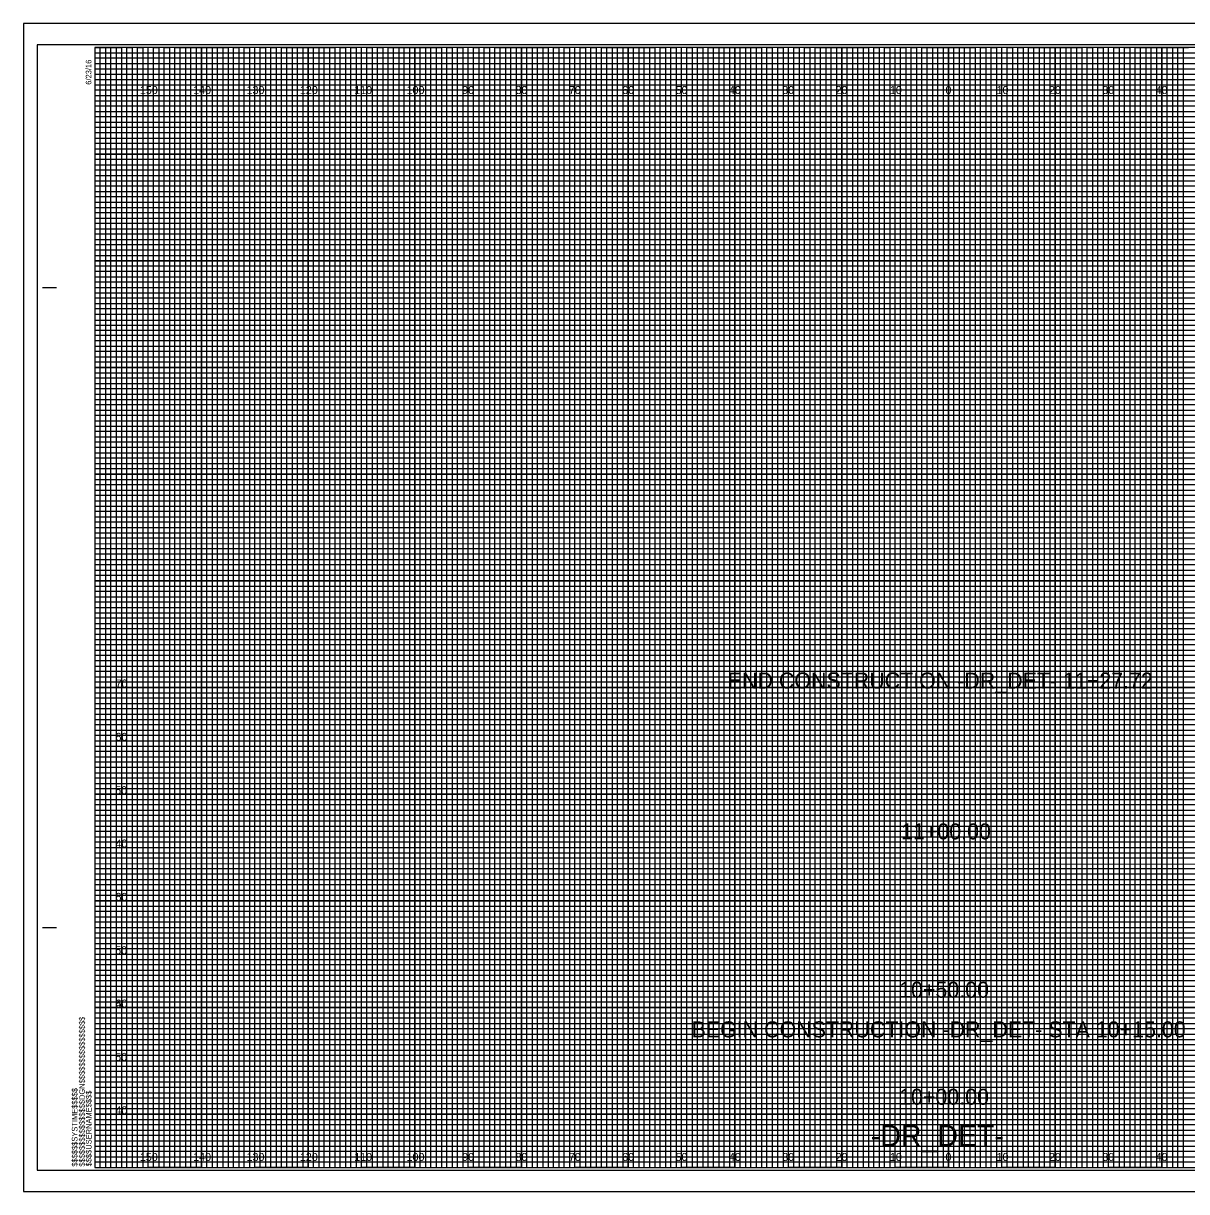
# Model space of a CAD drawing. Extents: x -13 to 323, y -5 to 215.
# Drawn here: x -13.4 to 204.7, y -4.5 to 214.5 of the extents above; entities that cross this region are included whole.
import ezdxf

# ---------------------------------------------------------------- set-up
doc = ezdxf.new("R2010")
doc.units = 0
for name, color, linetype in [('Prop XS Alignment Label', 7, 'Continuous'), ('Prop XS Elevation Labels', 7, 'Continuous'), ('Prop XS Offset Labels', 7, 'Continuous'), ('Prop XS Station Labels', 7, 'Continuous'), ('Sheet Cross Section CELL', 7, 'Continuous'), ('Sheet Cross Section Grid Major CELL', 7, 'Continuous'), ('Sheet Cross Section Grid Middle CELL', 7, 'Continuous'), ('Sheet Cross Section Grid Minor 1 CELL', 7, 'Continuous'), ('Sheet Cross Section Grid Minor 2 CELL', 7, 'Continuous'), ('Sheet Cutting Line CELL', 7, 'Continuous'), ('Sheet DOT Grid CELL', 7, 'Continuous'), ('Sheet Plot Border Inside CELL', 7, 'Continuous'), ('Sheet Plot Border Outside CELL', 7, 'Continuous')]:
    doc.layers.add(name, color=color, linetype=linetype)

msp = doc.modelspace()

# ---------------------------------------------------------------- linework, layer by layer
at = {"layer": 'Sheet Cross Section CELL'}
for p, q in [((-9.8, 165), (-7.3, 165)), ((-9.7, 165), (-7.2, 165)), ((-9.8, 45), (-7.3, 45)), ((-9.7, 45), (-7.2, 45)), ((0, 0), (0, 0)), ((0, 0), (0, 0)), ((0, 0), (0, 0)), ((0, 0), (0, 0)), ((0, 0), (0, 0)), ((0, 0), (0, 0)), ((0, 0), (0, 0))]:
    msp.add_line(p, q, dxfattribs=at)
msp.add_lwpolyline([(320, 210), (0, 210), (0, 0), (320, 0)], close=True, dxfattribs=at)
at = {"layer": 'Sheet Cross Section Grid Major CELL'}
for p, q in [((10, 210), (0, 210)), ((10, 0), (10, 210)), ((30, 210), (20, 210)), ((20, 210), (20, 0)), ((30, 0), (30, 210)), ((50, 210), (40, 210)), ((40, 210), (40, 0)), ((50, 0), (50, 210)), ((70, 210), (60, 210)), ((60, 210), (60, 0)), ((70, 0), (70, 210)), ((90, 210), (80, 210)), ((80, 210), (80, 0)), ((90, 0), (90, 210)), ((110, 210), (100, 210)), ((100, 210), (100, 0)), ((110, 0), (110, 210)), ((130, 210), (120, 210)), ((120, 210), (120, 0)), ((130, 0), (130, 210)), ((150, 210), (140, 210)), ((140, 210), (140, 0)), ((150, 0), (150, 210)), ((170, 210), (160, 210)), ((160, 210), (160, 0)), ((170, 0), (170, 210)), ((190, 210), (180, 210)), ((180, 210), (180, 0)), ((190, 0), (190, 210)), ((210, 210), (200, 210)), ((200, 210), (200, 0)), ((20, 0), (10, 0)), ((40, 0), (30, 0)), ((60, 0), (50, 0)), ((80, 0), (70, 0)), ((100, 0), (90, 0)), ((120, 0), (110, 0)), ((140, 0), (130, 0)), ((160, 0), (150, 0)), ((180, 0), (170, 0)), ((200, 0), (190, 0))]:
    msp.add_line(p, q, dxfattribs=at)
for points in [[(0, 200), (320, 200), (320, 190), (0, 190)], [(0, 180), (320, 180), (320, 170), (0, 170)], [(0, 160), (320, 160), (320, 150), (0, 150)], [(0, 140), (320, 140), (320, 130), (0, 130)], [(0, 120), (320, 120), (320, 110), (0, 110)], [(0, 100), (320, 100), (320, 90), (0, 90)], [(0, 80), (320, 80), (320, 70), (0, 70)], [(0, 60), (320, 60), (320, 50), (0, 50)], [(0, 40), (320, 40), (320, 30), (0, 30)], [(0, 20), (320, 20), (320, 10), (0, 10)]]:
    msp.add_lwpolyline(points, dxfattribs=at)
at = {"layer": 'Sheet Cross Section Grid Middle CELL'}
for points in [[(0, 210), (5, 210), (5, 0), (15, 0), (15, 210), (25, 210), (25, 0), (35, 0), (35, 210), (45, 210), (45, 0), (55, 0), (55, 210), (65, 210), (65, 0), (75, 0), (75, 210), (85, 210), (85, 0), (95, 0), (95, 210), (105, 210), (105, 0), (115, 0), (115, 210), (125, 210), (125, 0), (135, 0), (135, 210), (145, 210), (145, 0), (155, 0), (155, 210), (165, 210), (165, 0), (175, 0), (175, 210), (185, 210), (185, 0), (195, 0), (195, 210), (205, 210)], [(0, 205), (275, 205)], [(0, 185), (320, 185), (320, 195), (0, 195)], [(0, 165), (320, 165), (320, 175), (0, 175)], [(0, 145), (320, 145), (320, 155), (0, 155)], [(0, 125), (320, 125), (320, 135), (0, 135)], [(0, 105), (320, 105), (320, 115), (0, 115)], [(0, 85), (320, 85), (320, 95), (0, 95)], [(0, 65), (320, 65), (320, 75), (0, 75)], [(0, 45), (320, 45), (320, 55), (0, 55)], [(0, 25), (320, 25), (320, 35), (0, 35)], [(0, 5), (320, 5), (320, 15), (0, 15)]]:
    msp.add_lwpolyline(points, dxfattribs=at)
at = {"layer": 'Sheet Cross Section Grid Minor 1 CELL'}
for p, q in [((0, 209), (260, 209)), ((260, 207.98), (0, 207.98)), ((0, 207.98), (0, 207)), ((0, 207), (260, 207)), ((260, 205.89), (0, 205.89)), ((0, 205.89), (0, 204)), ((0, 204), (320, 204))]:
    msp.add_line(p, q, dxfattribs=at)
for points in [[(0, 203), (270, 203), (320, 203), (320, 202), (0, 202)], [(0, 201), (320, 201), (320, 199), (0, 199)], [(0, 198), (320, 198), (320, 197), (0, 196.98)], [(0, 196), (320, 196), (320, 194), (0, 194)], [(0, 193), (320, 193), (320, 192), (0, 192)], [(0, 191), (320, 191), (320, 189), (0, 189)], [(0, 188), (320, 188), (320, 187), (0, 187)], [(0, 186), (320, 186), (320, 184), (0, 184)], [(0, 183), (320, 183), (320, 182), (0, 182)], [(0, 181), (320, 181), (320, 179), (0, 179)], [(0, 178), (320, 178), (320, 177), (0, 177)], [(0, 176), (320, 176), (320, 173.95), (320, 173), (320, 172), (0, 172)], [(0, 174), (320, 174), (320, 173), (0, 173)], [(0, 171), (320, 171), (320, 169), (0, 169.03)], [(0, 169.03), (320, 169), (320, 168), (0, 168)], [(0, 167), (320, 167), (320, 166), (0, 166)], [(0, 164), (320, 164), (320, 163), (0, 163)], [(0, 162), (320, 162), (320, 161), (0, 161)], [(-0.07, 158.89), (320, 158.89), (320, 157.88), (-0.07, 157.88)], [(0, 157), (320, 157), (320, 156), (0, 156)], [(0, 154), (320, 154), (320, 153), (0, 153)], [(0, 152), (320, 152), (320, 151), (0, 151)], [(0, 149), (320, 149), (320, 148), (0, 148)], [(0, 147), (320, 147), (320, 146), (0, 146)], [(0, 144), (320, 144), (320, 143), (0, 143)], [(0, 142), (320, 142), (320, 141), (0, 141)], [(0, 139), (320, 139), (319.99, 137.98), (0, 138)], [(0, 137), (320, 137), (320, 136), (0, 136)], [(0, 134), (320, 134), (320, 133), (0, 133)], [(0, 132), (320, 132), (320, 131), (0, 131)], [(0, 129), (320, 129), (320, 128), (0, 128)], [(0, 127), (320, 127), (320, 126), (0, 126)], [(0, 124), (320, 124), (320, 123), (0, 123)], [(0, 122), (320, 122), (320, 121), (0, 121)], [(0, 119), (320, 119), (320, 118), (0, 118)], [(0, 116.99), (320.07, 116.91), (320, 116), (0, 116)], [(0, 114), (320, 114), (320, 113), (0, 113)], [(0, 112), (320, 112), (320, 111), (0, 111)], [(0, 109), (320, 109), (320, 108), (0, 108)], [(0, 107), (320, 107), (320, 106), (0, 106)], [(0, 104), (320, 104), (320, 103), (0, 103)], [(0, 102), (320, 102), (320, 101), (0, 101)], [(0, 99), (320, 99), (320, 98), (0, 98)], [(0, 97), (320, 97), (320, 96), (0, 96)], [(0, 94), (320, 94), (320, 93), (0, 93)], [(0, 92), (320, 92), (320, 91), (0, 91)], [(0, 89), (320, 89), (320, 88), (0, 88)], [(0, 87), (320, 87), (320, 86), (0, 86)], [(0, 84), (320, 84), (320, 83), (0, 83)], [(0, 82), (320, 82), (320, 81), (0, 81)], [(0, 79), (320, 79), (319.99, 77.98), (0, 78)], [(0, 77), (320, 77), (320, 76), (0, 76)], [(0, 74), (320, 74), (320, 73), (0, 73)], [(0, 72), (320, 72), (320, 71), (0, 71)], [(0, 69), (320, 69), (320, 68), (0, 68)], [(0, 67), (320, 67), (320, 66), (0, 66)], [(0, 64), (320, 64), (320, 63), (0, 63)], [(0, 62), (320, 62), (320, 61), (0, 61)], [(0, 59), (320, 59), (320, 58), (0, 58)], [(0, 56.99), (320.07, 56.91), (320, 56), (0, 56)], [(0, 54), (320, 54), (320, 53), (0, 53)], [(0, 52), (320, 52), (320, 51), (0, 51)], [(0, 49), (320, 49), (320, 48), (0, 48)], [(0, 47), (320, 47), (320, 46), (0, 46)], [(0, 44), (320, 44), (320, 43), (0, 43)], [(0, 42), (320, 42), (320, 41), (0, 41)], [(0, 39), (320, 39), (320, 38), (0, 38)], [(0, 37), (320, 37), (320, 36), (0, 36)], [(0, 34), (320, 34), (320, 33), (0, 33)], [(0, 32), (320, 32), (320, 31), (0, 31)], [(0, 29), (320, 29), (320, 28), (0, 28)], [(0, 27), (320, 27), (320, 26), (0, 26)], [(0, 24), (320, 24), (320, 23), (0, 23)], [(0, 22), (320, 22), (320, 21), (0, 21)], [(0, 19), (320, 19), (320, 18), (0, 18)], [(0, 17), (320, 17), (320, 16), (0, 16)], [(0, 14), (320, 14), (320, 13), (0, 13)], [(0, 12), (320, 12), (320, 11), (0, 11)], [(0, 9), (320, 9), (320, 8), (0, 8)], [(0, 7), (320, 7), (320, 6), (0, 6)], [(0, 4), (320, 4), (320, 3), (0, 3)], [(0, 2), (320, 2), (320, 1), (0, 1)]]:
    msp.add_lwpolyline(points, dxfattribs=at)
at = {"layer": 'Sheet Cross Section Grid Minor 2 CELL'}
for points in [[(0, 0), (1, 0), (1, 210), (2, 210), (2, 0)], [(2, 0), (3, 0), (3, 210), (4, 210), (4, 0)], [(5, 0), (6, 0), (6, 210), (7, 210), (7, 0)], [(7, 0), (8, 0), (8, 210), (9, 210), (9, 0)], [(10, 0), (11, 0), (11, 210), (12, 210), (12, 0)], [(12, 0), (13, 0), (13, 210), (14, 210), (14, 0)], [(15, 0), (16, 0), (16, 210), (17, 210), (17, 0)], [(17, 0), (18, 0), (18, 210), (19, 210), (19, 0)], [(20, 0), (21, 0), (21, 210), (22, 210), (22, 0)], [(22, 0), (23, 0), (23, 210), (24, 210), (24, 0)], [(25, 0), (26, 0), (26, 210), (27, 210), (27, 0)], [(27, 0), (28, 0), (28, 210), (29, 210), (29, 0)], [(30, 0), (31, 0), (31, 210), (32, 210), (32, 0)], [(32, 0), (33, 0), (33, 210), (34, 210), (34, 0)], [(35, 0), (36, 0), (36, 210), (37, 210), (37, 0)], [(37, 0), (38, 0), (38, 210), (39, 210), (39, 0)], [(40, 0), (41, 0), (41, 210), (42, 210), (42, 0)], [(42, 0), (43, 0), (43, 210), (44, 210), (44, 0)], [(45, 0), (46, 0), (46, 210), (47, 210), (47, 0)], [(47, 0), (48, 0), (48, 210), (49, 210), (49, 0)], [(50, 0), (51, 0), (51, 210), (52, 210), (52, 0)], [(52, 0), (53, 0), (53, 210), (54, 210), (54, 0)], [(55, 0), (56, 0), (56, 210), (57, 210), (57, 0)], [(57, 0), (58, 0), (58, 210), (59, 210), (59, 0)], [(60, 0), (61, 0), (61, 210), (62, 210), (62, 0)], [(62, 0), (63, 0), (63, 210), (64, 210), (64, 0)], [(65, 0), (66, 0), (66, 210), (67, 210), (67, 0)], [(67, 0), (68, 0), (68, 210), (69, 210), (69, 0)], [(70, 0), (71, 0), (71, 210), (72, 210), (72, 0)], [(72, 0), (73, 0), (73, 210), (74, 210), (74, 0)], [(75, 0), (76, 0), (76, 210), (77, 210), (77, 0)], [(77, 0), (78, 0), (78, 210), (79, 210), (79, 0)], [(80, 0), (81, 0), (81, 210), (82, 210), (82, 0)], [(82, 0), (83, 0), (83, 210), (84, 210), (84, 0)], [(85, 0), (86, 0), (86, 210), (87, 210), (87, 0)], [(87, 0), (88, 0), (88, 210), (89, 210), (89, 0)], [(90, 0), (91, 0), (91, 210), (92, 210), (92, 0)], [(92, 0), (93, 0), (93, 210), (94, 210), (94, 0)], [(95, 0), (96, 0), (96, 210), (97, 210), (97, 0)], [(97, 0), (98, 0), (98, 210), (99, 210), (99, 0)], [(100, 0), (101, 0), (101, 210), (102, 210), (102, 0)], [(102, 0), (103, 0), (103, 210), (104, 210), (104, 0)], [(105, 0), (106, 0), (106, 210), (107, 210), (107, 0)], [(107, 0), (108, 0), (108, 210), (109, 210), (109, 0)], [(110, 0), (111, 0), (111, 210), (112, 210), (112, 0)], [(112, 0), (113, 0), (113, 210), (114, 210), (114, 0)], [(115, 0), (116, 0), (116, 210), (117, 210), (117, 0)], [(117, 0), (118, 0), (118, 210), (119, 210), (119, 0)], [(120, 0), (121, 0), (121, 210), (122, 210), (122, 0)], [(122, 0), (123, 0), (123, 210), (124, 210), (124, 0)], [(125, 0), (126, 0), (126, 210), (127, 210), (127, 0)], [(127, 0), (128, 0), (128, 210), (129, 210), (129, 0)], [(130, 0), (131, 0), (131, 210), (132, 210), (132, 0)], [(132, 0), (133, 0), (133, 210), (134, 210), (134, 0)], [(135, 0), (136, 0), (136, 210), (137, 210), (137, 0)], [(137, 0), (138, 0), (138, 210), (139, 210), (139, 0)], [(140, 0), (141, 0), (141, 210), (142, 210), (142, 0)], [(142, 0), (143, 0), (143, 210), (144, 210), (144, 0)], [(145, 0), (146, 0), (146, 210), (147, 210), (147, 0)], [(147, 0), (148, 0), (148, 210), (149, 210), (149, 0)], [(150, 0), (151, 0), (151, 210), (152, 210), (152, 0)], [(152, 0), (153, 0), (153, 210), (154, 210), (154, 0)], [(155, 0), (156, 0), (156, 210), (157, 210), (157, 0)], [(157, 0), (158, 0), (158, 210), (159, 210), (159, 0)], [(160, 0), (161, 0), (161, 210), (162, 210), (162, 0)], [(162, 0), (163, 0), (163, 210), (164, 210), (164, 0)], [(165, 0), (166, 0), (166, 210), (167, 210), (167, 0)], [(167, 0), (168, 0), (168, 210), (169, 210), (169, 0)], [(170, 0), (171, 0), (171, 210), (172, 210), (172, 0)], [(172, 0), (173, 0), (173, 210), (174, 210), (174, 0)], [(175, 0), (176, 0), (176, 210), (177, 210), (177, 0)], [(177, 0), (178, 0), (178, 210), (179, 210), (179, 0)], [(180, 0), (181, 0), (181, 210), (182, 210), (182, 0)], [(182, 0), (183, 0), (183, 210), (184, 210), (184, 0)], [(185, 0), (186, 0), (186, 210), (187, 210), (187, 0)], [(187, 0), (188, 0), (188, 210), (189, 210), (189, 0)], [(190, 0), (191, 0), (191, 210), (192, 210), (192, 0)], [(192, 0), (193, 0), (193, 210), (194, 210), (194, 0)], [(195, 0), (196, 0), (196, 210), (197, 210), (197, 0)], [(197, 0), (198, 0), (198, 210), (199, 210), (199, 0)], [(200, 0), (201, 0), (201, 210), (202, 210), (202, 0)], [(202, 0), (203, 0), (203, 210), (204, 210), (204, 0)]]:
    msp.add_lwpolyline(points, dxfattribs=at)
at = {"layer": 'Sheet Cutting Line CELL'}
for p, q in [((323.3, 214.5), (-13.4, 214.5)), ((-13.4, 214.5), (-13.4, -4.5)), ((-13.4, -4.5), (323.3, -4.5))]:
    msp.add_line(p, q, dxfattribs=at)
at = {"layer": 'Sheet DOT Grid CELL'}
for p, q in [((10, 0), (10, 210)), ((20, 0), (20, 210)), ((30, 0), (30, 210)), ((40, 0), (40, 210)), ((50, 0), (50, 210)), ((60, 0), (60, 210)), ((70, 0), (70, 210)), ((80, 0), (80, 210)), ((90, 0), (90, 210)), ((100, 0), (100, 210)), ((110, 0), (110, 210)), ((120, 0), (120, 210)), ((130, 0), (130, 210)), ((140, 0), (140, 210)), ((150, 0), (150, 210)), ((160, 0), (160, 210)), ((170, 0), (170, 210)), ((180, 0), (180, 210)), ((190, 0), (190, 210)), ((200, 0), (200, 210)), ((0, 200), (320, 200)), ((0, 190), (320, 190)), ((0, 180), (320, 180)), ((0, 170), (320, 170)), ((0, 160), (320, 160)), ((0, 150), (320, 150)), ((0, 140), (320, 140)), ((0, 130), (320, 130)), ((0, 120), (320, 120)), ((0, 110), (320, 110)), ((0, 100), (320, 100)), ((0, 90), (320, 90)), ((0, 80), (320, 80)), ((0, 70), (320, 70)), ((0, 60), (320, 60)), ((0, 50), (320, 50)), ((0, 40), (320, 40)), ((0, 30), (320, 30)), ((0, 20), (320, 20)), ((0, 10), (320, 10))]:
    msp.add_line(p, q, dxfattribs=at)
at = {"layer": 'Sheet Plot Border Inside CELL'}
msp.add_lwpolyline([(-10.8, -0.5), (322.4, -0.5), (322.4, 210.5), (-10.8, 210.5)], close=True, dxfattribs=at)
at = {"layer": 'Sheet Plot Border Outside CELL'}
msp.add_lwpolyline([(-13.4, -4.5), (323.3, -4.5), (323.3, 214.5), (-13.4, 214.5)], close=True, dxfattribs=at)

# ---------------------------------------------------------------- texts
at = {"layer": 'Prop XS Alignment Label'}
msp.add_text('-DR_DET-', height=4, dxfattribs=at).set_placement((145.46, 4))
at = {"layer": 'Prop XS Elevation Labels'}
for s, p in [('70', (3.9, 90)), ('60', (3.87, 80)), ('50', (3.82, 70)), ('40', (3.87, 60)), ('60', (3.87, 50)), ('50', (3.82, 40)), ('40', (3.87, 30)), ('60', (3.87, 30)), ('50', (3.82, 20)), ('40', (3.87, 10))]:
    msp.add_text(s, height=1.5, dxfattribs=at).set_placement(p)
at = {"layer": 'Prop XS Offset Labels'}
for s, p in [('150', (8.44, 201.25)), ('140', (18.44, 201.25)), ('130', (28.44, 201.25)), ('120', (38.44, 201.25)), ('110', (48.62, 201.25)), ('100', (58.44, 201.25)), ('90', (68.86, 201.25)), ('80', (78.86, 201.25)), ('70', (88.86, 201.25)), ('60', (98.86, 201.25)), ('50', (108.86, 201.25)), ('40', (118.86, 201.25)), ('30', (128.86, 201.25)), ('20', (138.86, 201.25)), ('10', (149.04, 201.25)), ('0', (159.45, 201.25)), ('0', (159.45, 201.25)), ('10', (169.04, 201.25)), ('20', (178.86, 201.25)), ('30', (188.86, 201.25)), ('40', (198.86, 201.25)), ('150', (8.44, 1.25)), ('140', (18.44, 1.25)), ('130', (28.44, 1.25)), ('120', (38.44, 1.25)), ('110', (48.62, 1.25)), ('100', (58.44, 1.25)), ('90', (68.86, 1.25)), ('80', (78.86, 1.25)), ('70', (88.86, 1.25)), ('60', (98.86, 1.25)), ('50', (108.86, 1.25)), ('40', (118.86, 1.25)), ('30', (128.86, 1.25)), ('20', (138.86, 1.25)), ('10', (149.04, 1.25)), ('0', (159.45, 1.25)), ('0', (159.45, 1.25)), ('10', (169.04, 1.25)), ('20', (178.86, 1.25)), ('30', (188.86, 1.25)), ('40', (198.86, 1.25))]:
    msp.add_text(s, height=1.5, dxfattribs=at).set_placement(p)
at = {"layer": 'Prop XS Station Labels'}
for s, p in [('END CONSTRUCTION -DR_DET- 11+27.72', (118.64, 89.81)), ('11+00.00', (151.13, 61.53)), ('10+50.00', (150.77, 31.85)), ('BEGIN CONSTRUCTION -DR_DET- STA 10+15.00', (111.86, 24.42)), ('10+00.00', (150.77, 11.79))]:
    msp.add_text(s, height=3, dxfattribs=at).set_placement(p)
at = {"layer": 'Sheet Cross Section CELL'}
for s, p in [('6/23/16', (-0.65, 203)), ('$$$$$$$$$$$$$$$$DGN$$$$$$$$$$$$$$$$', (-1.88, 0.18)), ('$$$$$$SYSTIME$$$$$', (-3.26, 0.18)), ('$$$$USERNAME$$$$', (-0.62, 0.23))]:
    msp.add_text(s, height=1.05, rotation=90, dxfattribs=at).set_placement(p)

doc.saveas('drawing.dxf')
